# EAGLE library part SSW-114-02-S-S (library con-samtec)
THROUGH-HOLE .025" SQ POST SOCKET Source: Samtec SSW.pdf
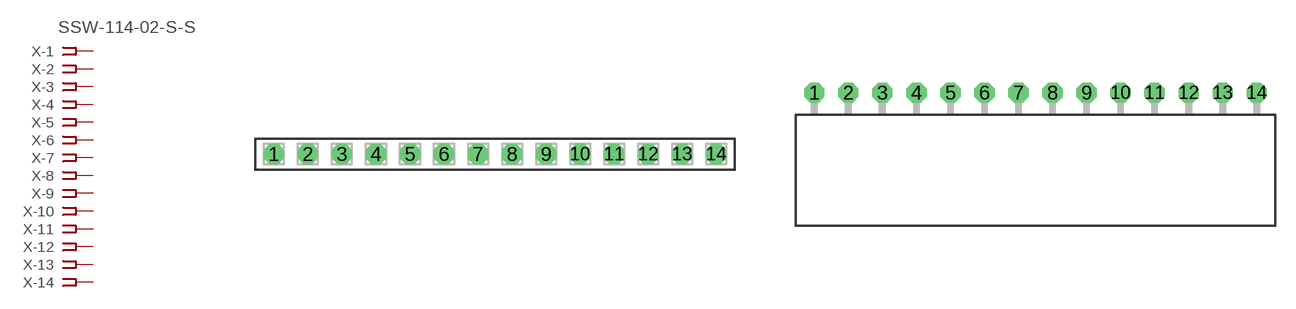
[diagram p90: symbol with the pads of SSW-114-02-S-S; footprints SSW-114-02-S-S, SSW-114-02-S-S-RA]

Designator prefix X; gates -1=FPINV -2=FPIN -3=FPIN -4=FPIN -5=FPIN -6=FPIN -7=FPIN -8=FPIN -9=FPIN -10=FPIN -11=FPIN -12=FPIN -13=FPIN -14=FPIN

## SSW-114-02-S-S (MPN: SSW-114-02-S-S; OC_FARNELL: unknown; OC_NEWARK: 11P9549)  [SSW-114-02-S-S]
1  -1:1  pas
2  -2:1  pas
3  -3:1  pas
4  -4:1  pas
5  -5:1  pas
6  -6:1  pas
7  -7:1  pas
8  -8:1  pas
9  -9:1  pas
10  -10:1  pas
11  -11:1  pas
12  -12:1  pas
13  -13:1  pas
14  -14:1  pas

## SSW-114-02-S-S-RA (MPN: SSW-114-02-S-S-RA; OC_FARNELL: unknown; OC_NEWARK: 11P9550)  [SSW-114-02-S-S-RA]
Pads as for SSW-114-02-S-S

## Footprint SSW-114-02-S-S (pad centres in mm)
THROUGH-HOLE .025" SQ POST SOCKET Source: Samtec SSW.pdf
drill 1 pad 1.5 octagon: 1 -16.51,0; 2 -13.97,0; 3 -11.43,0; 4 -8.89,0; 5 -6.35,0; 6 -3.81,0; 7 -1.27,0; 8 1.27,0; 9 3.81,0; 10 6.35,0; 11 8.89,0; 12 11.43,0; 13 13.97,0; 14 16.51,0

## Footprint SSW-114-02-S-S-RA (pad centres in mm)
THROUGH-HOLE .025" SQ POST SOCKET Source: Samtec SSW.pdf
drill 1 pad 1.5 octagon: 1 -16.51,1.524; 2 -13.97,1.524; 3 -11.43,1.524; 4 -8.89,1.524; 5 -6.35,1.524; 6 -3.81,1.524; 7 -1.27,1.524; 8 1.27,1.524; 9 3.81,1.524; 10 6.35,1.524; 11 8.89,1.524; 12 11.43,1.524; 13 13.97,1.524; 14 16.51,1.524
